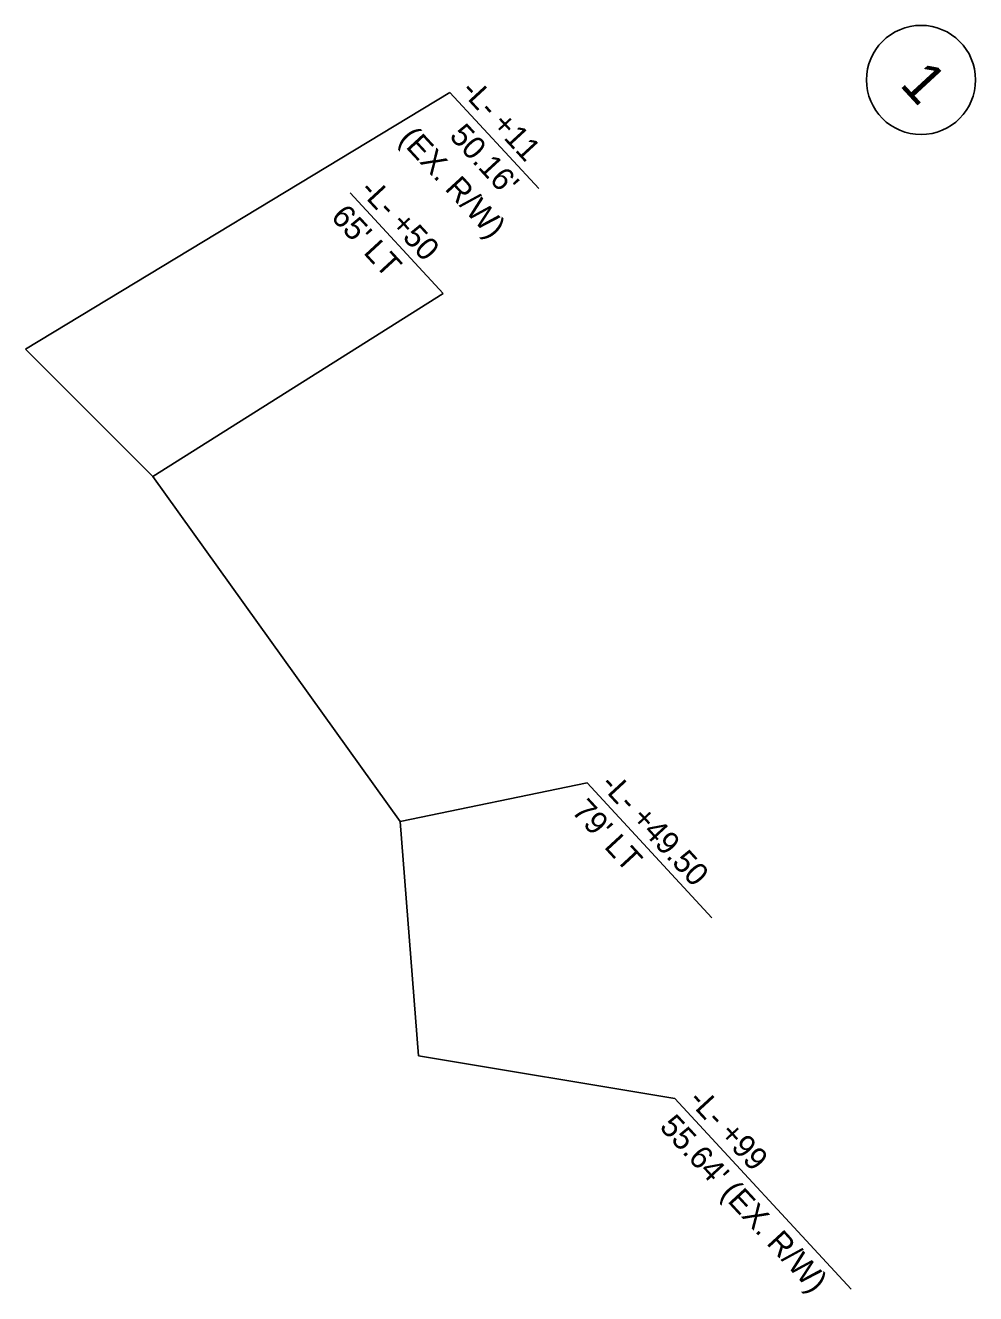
# Model space of a CAD drawing. Extents: x 1703100 to 1704058, y 794243 to 795715.
# Drawn here: x 1703100.4 to 1703309.3, y 795435.7 to 795714.8 of the extents above; entities that cross this region are included whole.
import ezdxf

# ---------------------------------------------------------------- set-up
doc = ezdxf.new("R2010")
doc.units = 0
for name, color, linetype in [('Prop Easement Construction', 7, 'Continuous'), ('Prop Easement Construction Station Offsets', 7, 'Continuous'), ('Prop Parcel Number CELL', 7, 'Continuous'), ('Prop Parcel Number Text', 7, 'Continuous')]:
    doc.layers.add(name, color=color, linetype=linetype)

msp = doc.modelspace()

# ---------------------------------------------------------------- linework, layer by layer
at = {"layer": 'Prop Easement Construction'}
for p, q in [((1703100.36, 795643.51), (1703128.4, 795615.5)), ((1703128.4, 795615.5), (1703182.78, 795539.62)), ((1703182.78, 795539.62), (1703186.79, 795488.04))]:
    msp.add_line(p, q, dxfattribs=at)
at = {"layer": 'Prop Easement Construction Station Offsets'}
for p, q in [((1703100.36, 795643.51), (1703193.73, 795699.99)), ((1703193.73, 795699.99), (1703213.23, 795678.86)), ((1703171.79, 795677.94), (1703192.25, 795655.78)), ((1703192.25, 795655.78), (1703128.4, 795615.5)), ((1703182.78, 795539.62), (1703223.87, 795548.1)), ((1703223.87, 795548.1), (1703251.3, 795518.39)), ((1703186.79, 795488.04), (1703243.2, 795478.66)), ((1703243.2, 795478.66), (1703281.96, 795436.67))]:
    msp.add_line(p, q, dxfattribs=at)
at = {"layer": 'Prop Parcel Number CELL'}
msp.add_line((1703297.31, 795702.76), (1703297.31, 795702.76), dxfattribs=at)
msp.add_circle((1703297.31, 795702.76), 12, dxfattribs=at)

# ---------------------------------------------------------------- texts
at = {"layer": 'Prop Easement Construction Station Offsets'}
for s, p in [('-L- +11', (1703195.9, 795700.18)), ("50.16'", (1703193.4, 795690.25)), ('(EX. R/W)', (1703182.32, 795689.62)), ('-L- +50', (1703173.64, 795678.27)), ("65' LT  ", (1703167.34, 795672.45)), ('-L- +49.50', (1703226.57, 795547.51)), ("79' LT  ", (1703220.27, 795541.7)), ('-L- +99', (1703245.9, 795478.06)), ("55.64' (EX. R/W) ", (1703239.6, 795472.25))]:
    msp.add_text(s, height=5, rotation=312.7091, dxfattribs=at).set_placement(p)
at = {"layer": 'Prop Parcel Number Text'}
msp.add_text('1', height=9, rotation=312.7091, dxfattribs=at).set_placement((1703292.4, 795701.64))

doc.saveas('drawing.dxf')
